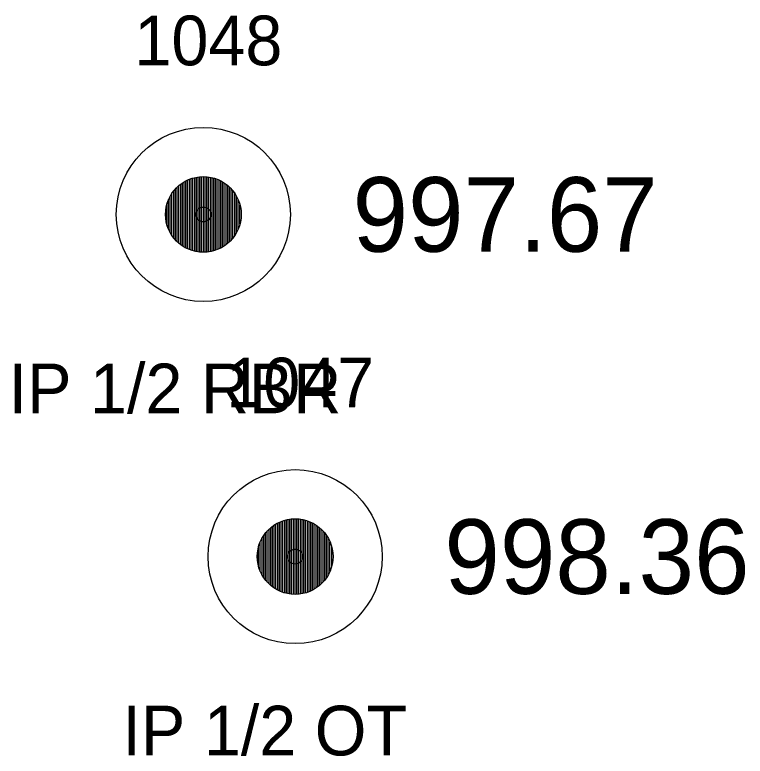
# Model space of a CAD drawing. Extents: x 1578957 to 1581675, y 1115963 to 1120391.
# Drawn here: x 1579112.91 to 1579127.59, y 1117023.19 to 1117038.1 of the extents above; entities that cross this region are included whole.
import ezdxf

# ---------------------------------------------------------------- set-up
doc = ezdxf.new("R2010")
doc.units = 0
for name, color, linetype in [('RD_EX_DV_Prop_txCode', 7, 'Continuous'), ('RD_EX_DV_PropPin', 7, 'Continuous'), ('RD_EX_TX_DV_Prop_ELEV', 7, 'Continuous'), ('RD_SMD_Locator', 7, 'Continuous')]:
    doc.layers.add(name, color=color, linetype=linetype)

msp = doc.modelspace()

# ---------------------------------------------------------------- linework, layer by layer
at = {"layer": 'RD_EX_DV_PropPin'}
for p, q in [((1579116.626, 1117033.326), (1579116.626, 1117034.841)), ((1579116.661, 1117033.323), (1579116.661, 1117034.844)), ((1579116.696, 1117033.322), (1579116.696, 1117034.844)), ((1579116.731, 1117033.323), (1579116.731, 1117034.844)), ((1579116.766, 1117033.326), (1579116.766, 1117034.841)), ((1579116.24, 1117033.473), (1579116.24, 1117034.693)), ((1579116.275, 1117033.449), (1579116.275, 1117034.718)), ((1579116.31, 1117033.427), (1579116.31, 1117034.74)), ((1579116.345, 1117033.408), (1579116.345, 1117034.759)), ((1579116.38, 1117033.391), (1579116.38, 1117034.776)), ((1579116.415, 1117033.376), (1579116.415, 1117034.791)), ((1579116.45, 1117033.363), (1579116.45, 1117034.804)), ((1579116.485, 1117033.352), (1579116.485, 1117034.815)), ((1579116.521, 1117033.343), (1579116.521, 1117034.824)), ((1579116.556, 1117033.335), (1579116.556, 1117034.831)), ((1579116.591, 1117033.33), (1579116.591, 1117034.837)), ((1579116.801, 1117033.33), (1579116.801, 1117034.837)), ((1579116.836, 1117033.335), (1579116.836, 1117034.831)), ((1579116.871, 1117033.343), (1579116.871, 1117034.824)), ((1579116.906, 1117033.352), (1579116.906, 1117034.815)), ((1579116.941, 1117033.363), (1579116.941, 1117034.804)), ((1579116.976, 1117033.376), (1579116.976, 1117034.791)), ((1579117.011, 1117033.391), (1579117.011, 1117034.776)), ((1579117.046, 1117033.408), (1579117.046, 1117034.759)), ((1579117.081, 1117033.427), (1579117.081, 1117034.74)), ((1579117.116, 1117033.449), (1579117.116, 1117034.718)), ((1579117.151, 1117033.473), (1579117.151, 1117034.693)), ((1579116.1, 1117033.609), (1579116.1, 1117034.557)), ((1579116.135, 1117033.568), (1579116.135, 1117034.598)), ((1579116.17, 1117033.533), (1579116.17, 1117034.634)), ((1579116.205, 1117033.501), (1579116.205, 1117034.665)), ((1579117.186, 1117033.501), (1579117.186, 1117034.665)), ((1579117.221, 1117033.533), (1579117.221, 1117034.634)), ((1579117.256, 1117033.568), (1579117.256, 1117034.598)), ((1579117.291, 1117033.609), (1579117.291, 1117034.557)), ((1579116.03, 1117033.714), (1579116.03, 1117034.453)), ((1579116.065, 1117033.657), (1579116.065, 1117034.51)), ((1579117.326, 1117033.657), (1579117.326, 1117034.51)), ((1579117.361, 1117033.714), (1579117.361, 1117034.453)), ((1579115.96, 1117033.887), (1579115.96, 1117034.279)), ((1579115.995, 1117033.785), (1579115.995, 1117034.381)), ((1579117.396, 1117033.785), (1579117.396, 1117034.381)), ((1579117.431, 1117033.887), (1579117.431, 1117034.279)), ((1579118.121, 1117026.567), (1579118.121, 1117027.836)), ((1579118.156, 1117026.545), (1579118.156, 1117027.858)), ((1579118.191, 1117026.526), (1579118.191, 1117027.877)), ((1579118.226, 1117026.509), (1579118.226, 1117027.894)), ((1579118.261, 1117026.494), (1579118.261, 1117027.909)), ((1579118.296, 1117026.481), (1579118.296, 1117027.922)), ((1579118.331, 1117026.47), (1579118.331, 1117027.933)), ((1579118.366, 1117026.461), (1579118.366, 1117027.942)), ((1579118.401, 1117026.454), (1579118.401, 1117027.95)), ((1579118.436, 1117026.448), (1579118.436, 1117027.955)), ((1579118.471, 1117026.444), (1579118.471, 1117027.959)), ((1579118.506, 1117026.441), (1579118.506, 1117027.962)), ((1579118.541, 1117026.441), (1579118.541, 1117027.963)), ((1579118.576, 1117026.441), (1579118.576, 1117027.962)), ((1579118.611, 1117026.444), (1579118.611, 1117027.959)), ((1579118.646, 1117026.448), (1579118.646, 1117027.955)), ((1579118.681, 1117026.454), (1579118.681, 1117027.95)), ((1579118.716, 1117026.461), (1579118.716, 1117027.942)), ((1579118.751, 1117026.47), (1579118.751, 1117027.933)), ((1579118.786, 1117026.481), (1579118.786, 1117027.922)), ((1579118.821, 1117026.494), (1579118.821, 1117027.909)), ((1579118.856, 1117026.509), (1579118.856, 1117027.894)), ((1579118.891, 1117026.526), (1579118.891, 1117027.877)), ((1579118.926, 1117026.545), (1579118.926, 1117027.858)), ((1579118.961, 1117026.567), (1579118.961, 1117027.836)), ((1579117.981, 1117026.687), (1579117.981, 1117027.717)), ((1579118.016, 1117026.651), (1579118.016, 1117027.752)), ((1579118.051, 1117026.62), (1579118.051, 1117027.784)), ((1579118.086, 1117026.592), (1579118.086, 1117027.812)), ((1579118.996, 1117026.592), (1579118.996, 1117027.812)), ((1579119.031, 1117026.62), (1579119.031, 1117027.784)), ((1579119.066, 1117026.651), (1579119.066, 1117027.752)), ((1579119.101, 1117026.687), (1579119.101, 1117027.717)), ((1579117.876, 1117026.832), (1579117.876, 1117027.571)), ((1579117.911, 1117026.775), (1579117.911, 1117027.628)), ((1579117.946, 1117026.728), (1579117.946, 1117027.676)), ((1579119.136, 1117026.728), (1579119.136, 1117027.676)), ((1579119.171, 1117026.775), (1579119.171, 1117027.628)), ((1579119.206, 1117026.832), (1579119.206, 1117027.571)), ((1579117.806, 1117027.006), (1579117.806, 1117027.398)), ((1579117.841, 1117026.904), (1579117.841, 1117027.5)), ((1579119.241, 1117026.904), (1579119.241, 1117027.5)), ((1579119.276, 1117027.006), (1579119.276, 1117027.398))]:
    msp.add_line(p, q, dxfattribs=at)
for centre, radius in [((1579116.696, 1117034.083), 1.75), ((1579116.696, 1117034.083), 0.761), ((1579118.541, 1117027.202), 1.75), ((1579118.541, 1117027.202), 0.761)]:
    msp.add_circle(centre, radius, dxfattribs=at)
at = {"layer": 'RD_SMD_Locator'}
for centre in [(1579116.696, 1117034.083), (1579118.541, 1117027.202)]:
    msp.add_circle(centre, 0.15, dxfattribs=at)

# ---------------------------------------------------------------- texts
at = {"layer": 'RD_EX_DV_Prop_txCode'}
for s, p in [('1048', (1579115.31, 1117037.083)), ('IP 1/2 RBR', (1579112.782, 1117030.083)), ('1047', (1579117.155, 1117030.202)), ('IP 1/2 OT', (1579115.069, 1117023.202))]:
    msp.add_text(s, height=1, dxfattribs=at).set_placement(p)
at = {"layer": 'RD_EX_TX_DV_Prop_ELEV'}
for s, p in [('997.67', (1579119.696, 1117033.333)), ('998.36', (1579121.541, 1117026.452))]:
    msp.add_text(s, height=1.5, dxfattribs=at).set_placement(p)

doc.saveas('drawing.dxf')
